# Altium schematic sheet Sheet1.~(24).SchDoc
size A
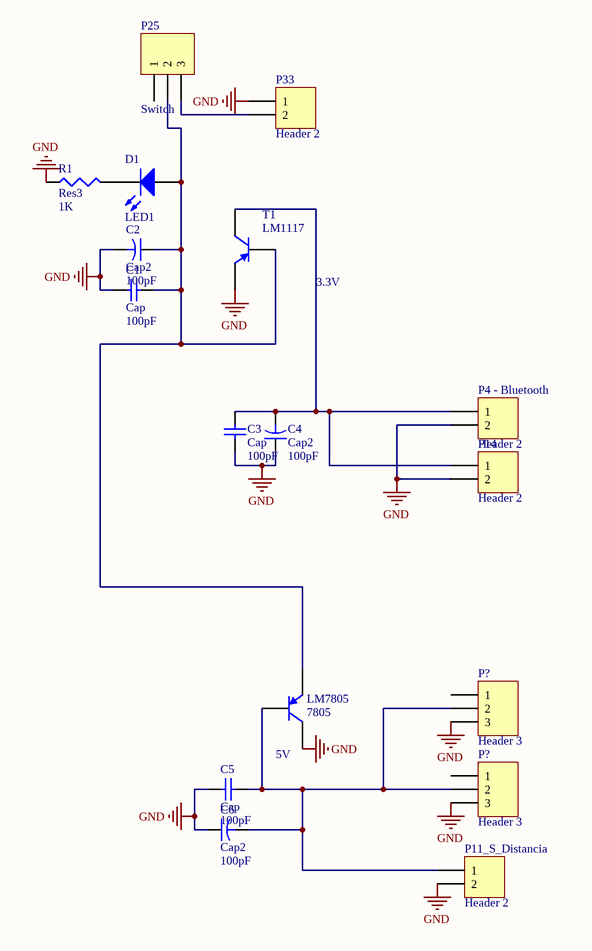
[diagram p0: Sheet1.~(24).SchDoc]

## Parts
(Parts that share a designator on the sheet are numbered #1, #2 ... from top to bottom, then left to right.)
C1  Cap  value 100pF  [RAD-0.2]
C2  Cap2  value 100pF  [CAPR5-4X5]
C3  Cap  value 100pF  [RAD-0.2]
C4  Cap2  value 100pF  [CAPR5-4X5]
C5  Cap  value 100pF  [RAD-0.2]
C6  Cap2  value 100pF  [CAPR5-4X5]
D1  LED1  [LED-1]
LM7805  7805  [TO-220-AB]
P4_-_Bluetooth  Header 2  [HDR1X2]
P11_S_Distancia  Header 2  [HDR1X2]
P14  Header 2  [HDR1X2]
P25  Switch  [HDR1X3]
P33  Header 2  [HDR1X2]
P?#1  Header 3  [HDR1X3]
P?#2  Header 3  [HDR1X3]
R1  Res3  value 1K  [J1-0603]
T1  LM1117  [TO-220-AB]

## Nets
GND: C1.1 C2.2 C3.2 C4.1 C5.2 C6.1 LM7805.2(B) P4_-_Bluetooth.2 P11_S_Distancia.2 P14.2 P33.1 P?#1.3 P?#2.3 R1.1 T1.1(E)
NetC1_2: C1.2 C2.1 D1.1(A) LM7805.1(E) P25.2 T1.3(C)
NetC3_1: C3.1 C4.2 P4_-_Bluetooth.1 P14.1 T1.2(B)
NetC5_1: C5.1 C6.2 LM7805.3(C) P11_S_Distancia.1 P?#1.2 P?#2.2
NetD1_2: D1.2(K) R1.2
NetP25_3: P25.3 P33.2

Not connected (* = marked no-connect by the designer): P25 1; P?#1 1; P?#2 1

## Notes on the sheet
- 3.3V
- (near LM7805) 5V

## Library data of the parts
C1 C3 C5 = Cap: Capacitor
C2 C4 C6 = Cap2: Capacitor
D1 = LED1: Typical RED GaAs LED
LM7805 T1 = 2N3906: PNP General Purpose Amplifier
P4_-_Bluetooth P11_S_Distancia P14 P33 = Header 2: Header, 2-Pin
P25 P?#1 P?#2 = Header 3: Header, 3-Pin
R1 = Res3: Resistor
